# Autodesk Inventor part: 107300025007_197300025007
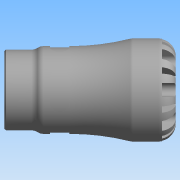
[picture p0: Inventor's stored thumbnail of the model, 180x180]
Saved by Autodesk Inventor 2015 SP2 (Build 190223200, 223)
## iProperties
Created: 2016-12
Part Number: 107300025007_197300025007
Material: Generic
Description: PLASSON FEMALE INTEGRAL BRASS THREAD 25X3/4" SERIES 1
Document SubType Name: Modeling
Designer: KIM
Density: 1 g/cm^3
Appearance: Default
Author: KIM
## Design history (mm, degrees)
derived "1073.ipt"
feature "Solid1::1073.ipt"
tag "TaggingFeature1"
body "Solid1"
other parameters: "d0" = 78, "d1" = 20.16, "d2" = 25, "d3" = 31.25, "d4" = 47, "d6" = 48, "d8" = 39.95, "d13" = 6.3, "d14" = 6.3, "d15" = 0, "d17" = 360 deg, "d19" = 8 deg, "d20" = 0.5, "d21" = 0.5, "d22" = 8 deg, "d24" = 0, "d26" = 360 deg, "d32" = 4.7, "d33" = 4.7, "d39" = 0.72351, "d42" = 24.117, "d43" = 36.66, "d46" = 2.08333, "d47" = 16, "d48" = 22.91115, "d50" = 4.62, "d51" = 0.47, "d54" = 8.75, "d55" = 5.5, "d57" = 12.348, "d58" = 0, "d68" = 360 deg, "d72" = 0.5, "d74" = 0, "d76" = 7.4375, "d_" = 25, "E_" = 47, "H_" = 78, "l_" = 48, "G_" = 24.117, "l_2" = 16, "d9" = 7.875, "d11" = 47, "d12" = 31.25, "d49" = 14
